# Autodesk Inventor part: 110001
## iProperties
Shininess: 64.0
Length Units: 11272
Angle Units: 11279
Time Units: 11290
Mass Units: 11286
Length Display Precision: 3
Angle Display Precision: 2
Compacted: True
Part Number: 110001
Document SubType Name: Modeling
Created: 2004-06
Designer: jpittman
Manufacturer: Standard
Standards Organization: Custom
Density: 0.0
Volumn: 0.0
Area: 0.0
PropertySet Name: Model Information
Control State: 0
Master: False
Checked Out: False
Translation Standard: STEP AP203
File Name: 110001
Preprocessor: PRO/ENGINEER BY PARAMETRIC TECHNOLOGY CORPORATION, 2001150
Postprocessor: Build: 081d, Release: 8 SP1 - Date: Tue 01/26/2004
Sent Units: INCHES
Uncertainty: 0.00019022974225369998
Author: jpittman
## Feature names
1. Base1
